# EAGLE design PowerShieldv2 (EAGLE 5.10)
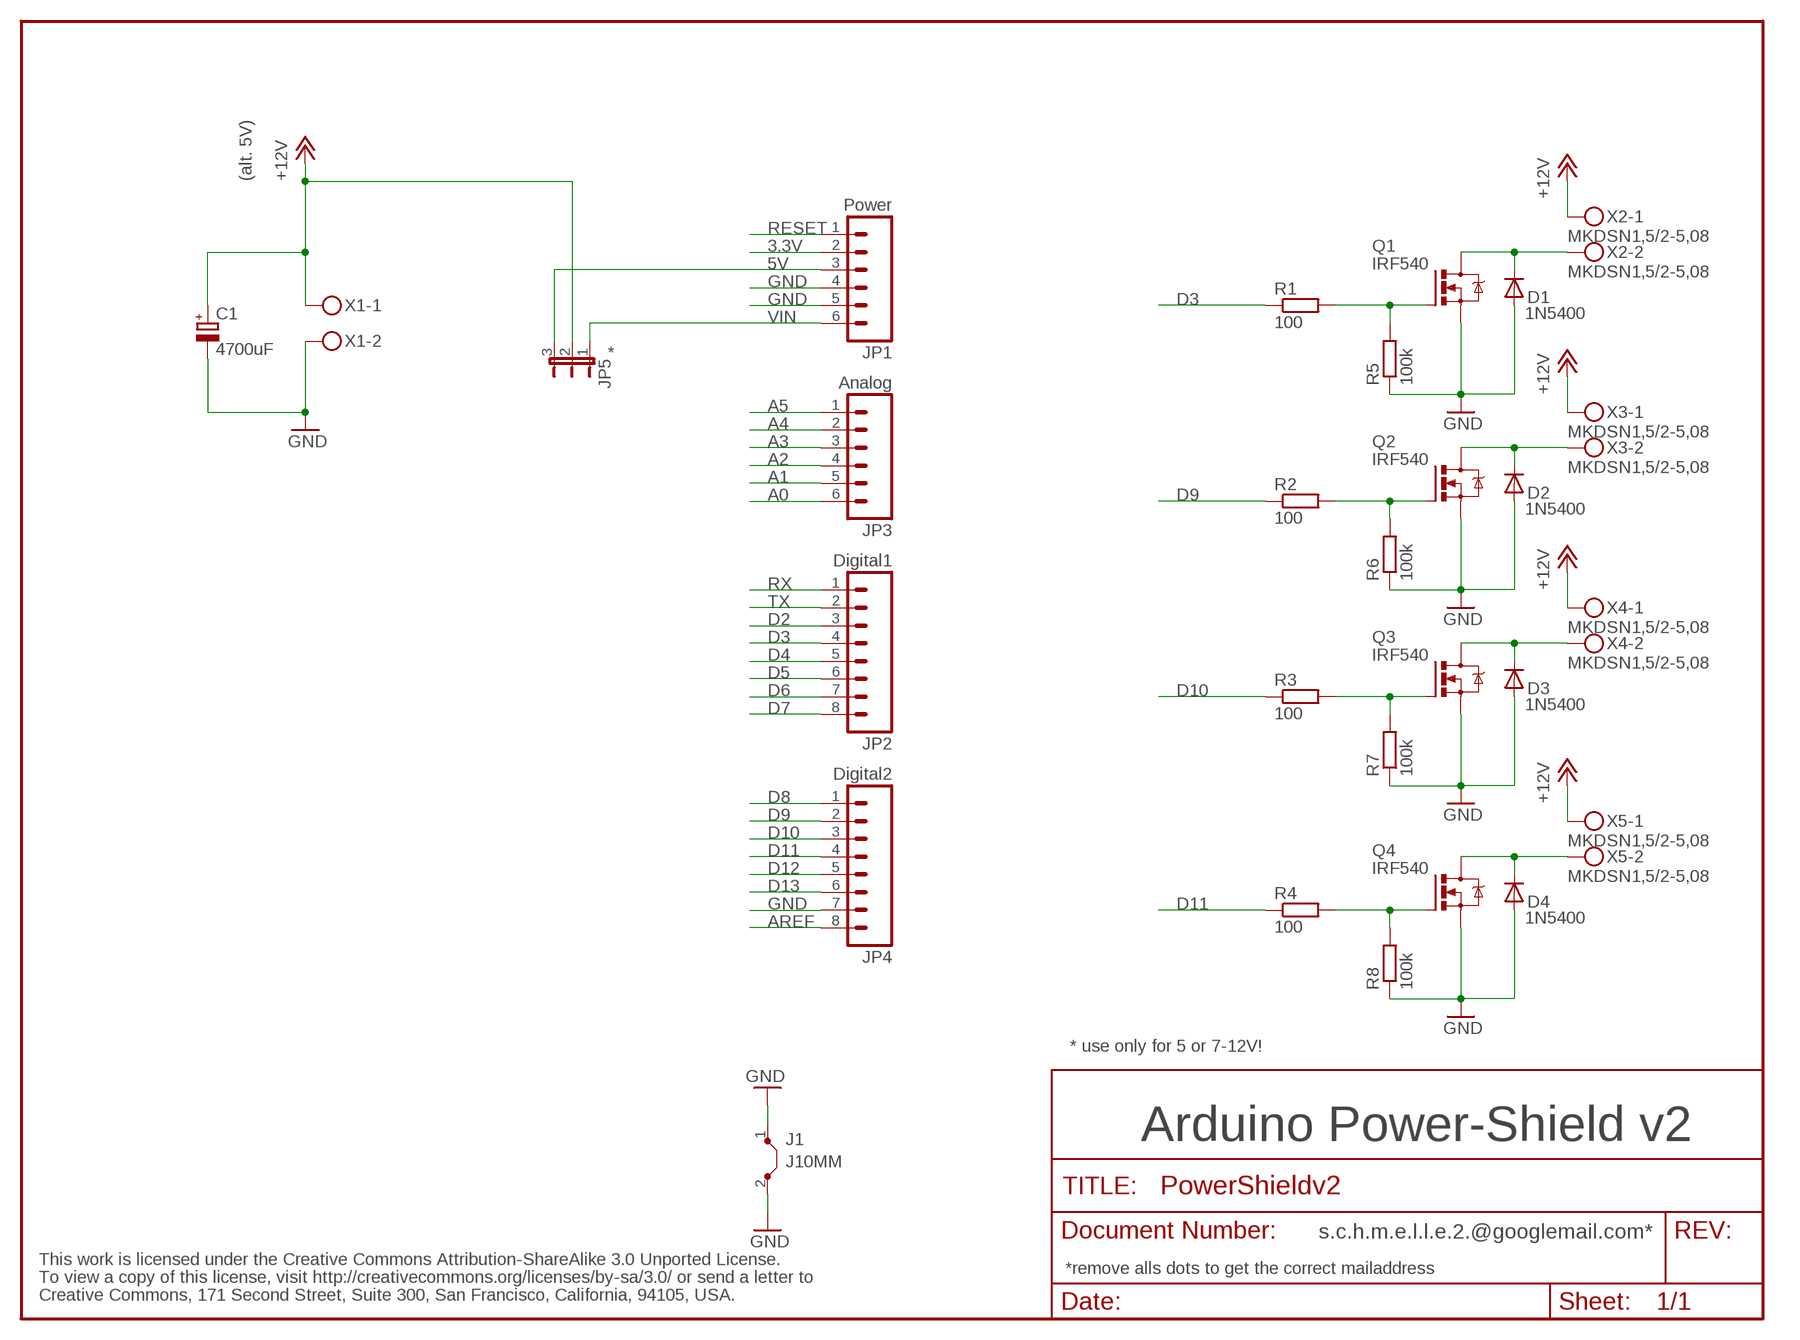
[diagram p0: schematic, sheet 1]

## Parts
C1  4700uF  CPOL-EUE35-16AXIAL  [E35-16]
D1  1N5400  [DO201-15]
D2  1N5400  [DO201-15]
D3  1N5400  [DO201-15]
D4  1N5400  [DO201-15]
J1  J10MM  [10]
JP1  Power  M06SIP  [1X06]
JP2  Digital1  M08  [1X08]
JP3  Analog  M06SIP  [1X06]
JP4  Digital2  M08  [1X08]
JP5  JP2E  [JP2]
Q1  IRF540  [TO220BV]
Q2  IRF540  [TO220BV]
Q3  IRF540  [TO220BV]
Q4  IRF540  [TO220BV]
R1  100  R-EU_0411/12  [0411/12]
R2  100  R-EU_0411/12  [0411/12]
R3  100  R-EU_0411/12  [0411/12]
R4  100  R-EU_0411/12  [0411/12]
R5  100k  R-EU_0411/12  [0411/12]
R6  100k  R-EU_0411/12  [0411/12]
R7  100k  R-EU_0411/12  [0411/12]
R8  100k  R-EU_0411/12  [0411/12]
X1  MKDSN1,5/2-5,08  [MKDSN1,5/2-5,08]
X2  MKDSN1,5/2-5,08  [MKDSN1,5/2-5,08]
X3  MKDSN1,5/2-5,08  [MKDSN1,5/2-5,08]
X4  MKDSN1,5/2-5,08  [MKDSN1,5/2-5,08]
X5  MKDSN1,5/2-5,08  [MKDSN1,5/2-5,08]

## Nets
3.3V: JP1.2
5V [power]: JP1.3 JP5.3
+12V: C1.+ JP5.2 X1.1 X2.1 X3.1 X4.1 X5.1
A0: JP3.6
A1: JP3.5
A2: JP3.4
A3: JP3.3
A4: JP3.2
A5: JP3.1
AREF: JP4.8
D2: JP2.3
D3: JP2.4 R1.1
D4: JP2.5
D5: JP2.6
D6: JP2.7
D7: JP2.8
D8: JP4.1
D9: JP4.2 R2.1
D10: JP4.3 R3.1
D11: JP4.4 R4.1
D12: JP4.5
D13: JP4.6
GND [power]: C1.- D1.A D2.A D3.A D4.A J1.1 J1.2 JP1.4 JP1.5 JP4.7 Q1.S Q2.S Q3.S Q4.S R5.1 R6.1 R7.1 R8.1 X1.2
N$1: D1.C Q1.D X2.2
N$2: Q1.G R1.2 R5.2
N$3: D2.C Q2.D X3.2
N$4: Q2.G R2.2 R6.2
N$5: D3.C Q3.D X4.2
N$6: Q3.G R3.2 R7.2
N$7: D4.C Q4.D X5.2
N$8: Q4.G R4.2 R8.2
RESET: JP1.1
RX: JP2.1
TX: JP2.2
VIN [power]: JP1.6 JP5.1

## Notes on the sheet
- (alt. 5V)
- *
- * use only for 5 or 7-12V!
- Arduino Power-Shield v2
- s.c.h.m.e.l.l.e.2.@googlemail.com*
- This work is licensed under the Creative Commons Attribution-ShareAlike 3.0 Unported License.
- *remove alls dots to get the correct mailaddress
- To view a copy of this license, visit http://creativecommons.org/licenses/by-sa/3.0/ or send a letter to
- Creative Commons, 171 Second Street, Suite 300, San Francisco, California, 94105, USA.

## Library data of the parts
C1 = resistor:CPOL-EU: POLARIZED CAPACITOR, European symbol
D1-D4 = diode:1N5400: DIODE
J1 = jumper:J: Bridge
JP1 JP3 = SparkFun:M06: Header 6 Standard 6-pin 0.1" header. Use with straight break away headers (SKU : PRT-00116), right angle break away headers (PRT-00553), swiss pins (PRT-00743), machine pins (PRT-00117), and female headers (PRT-00115). Molex polarized connector foot print use with SKU : PRT-08094 with associated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
JP2 JP4 = SparkFun:M08: Header 8 Standard 8-pin 0.1" header. Use with straight break away headers (SKU : PRT-00116), right angle break away headers (PRT-00553), swiss pins (PRT-00743), machine pins (PRT-00117), and female headers (PRT-00115).
JP5 = jumper:JP2E: JUMPER
Q1-Q4 = transistor-power:IRF540: HEXFET Power MOSFET
R1-R8 = resistor:R-EU_: RESISTOR, European symbol
X1-X5 = con-phoenix-508:MKDSN1,5/2-5,08: MKDSN 1,5/ 2-5,08 Printklemme

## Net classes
1 power: width 0.254 mm

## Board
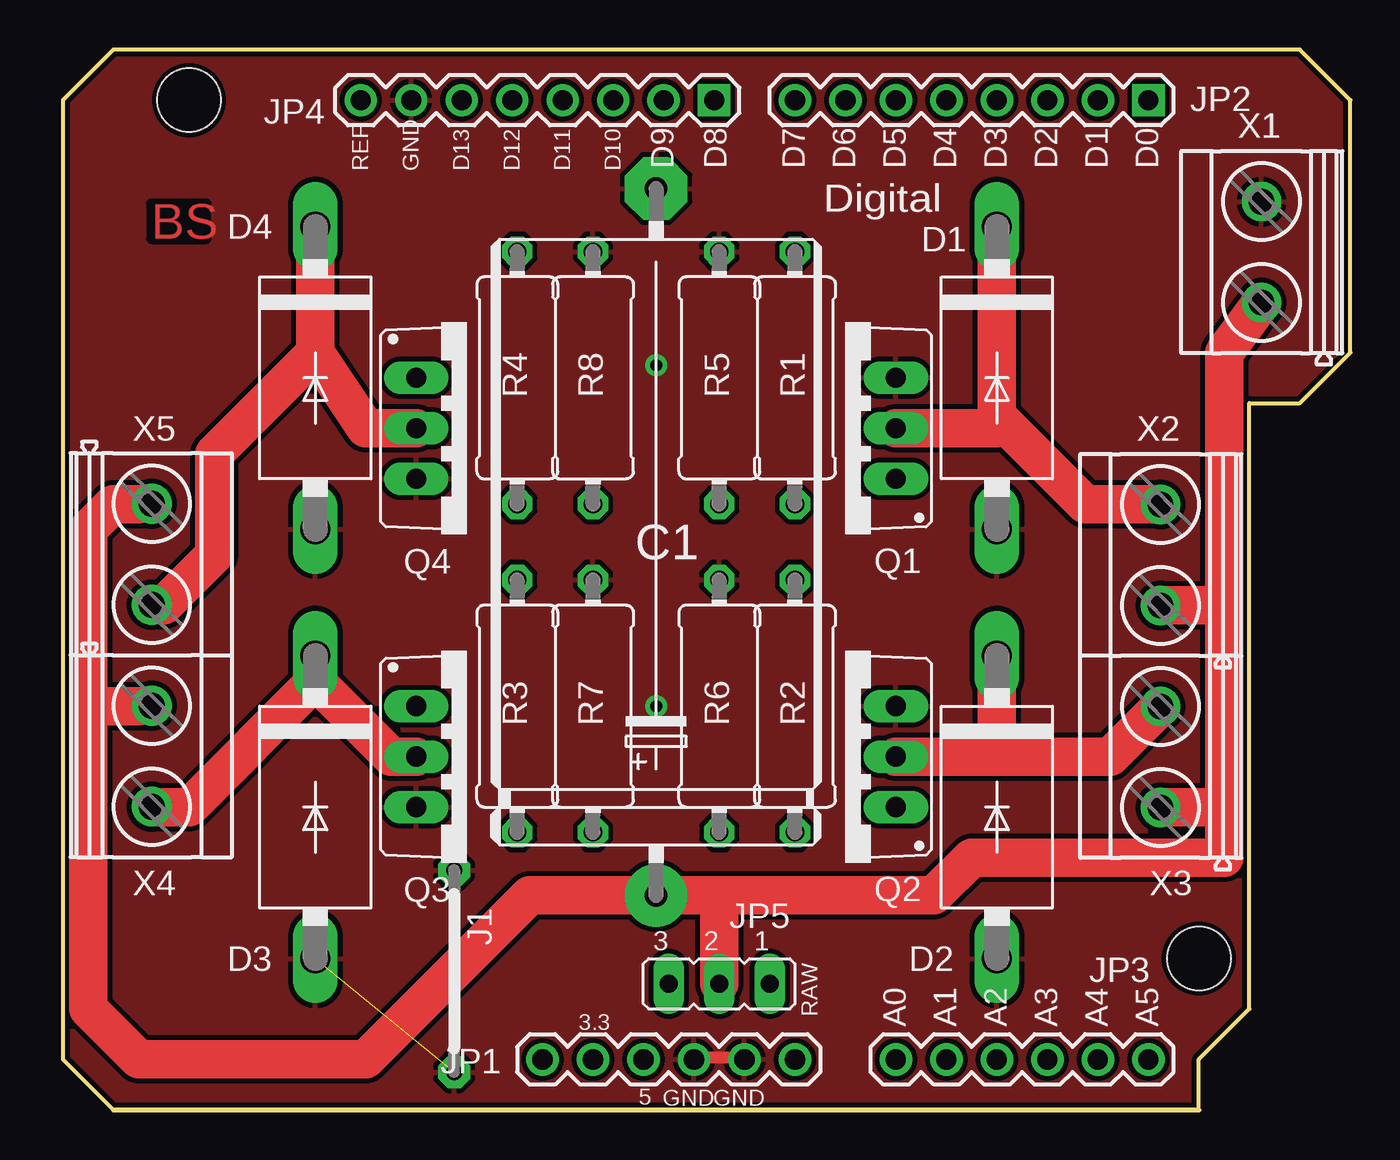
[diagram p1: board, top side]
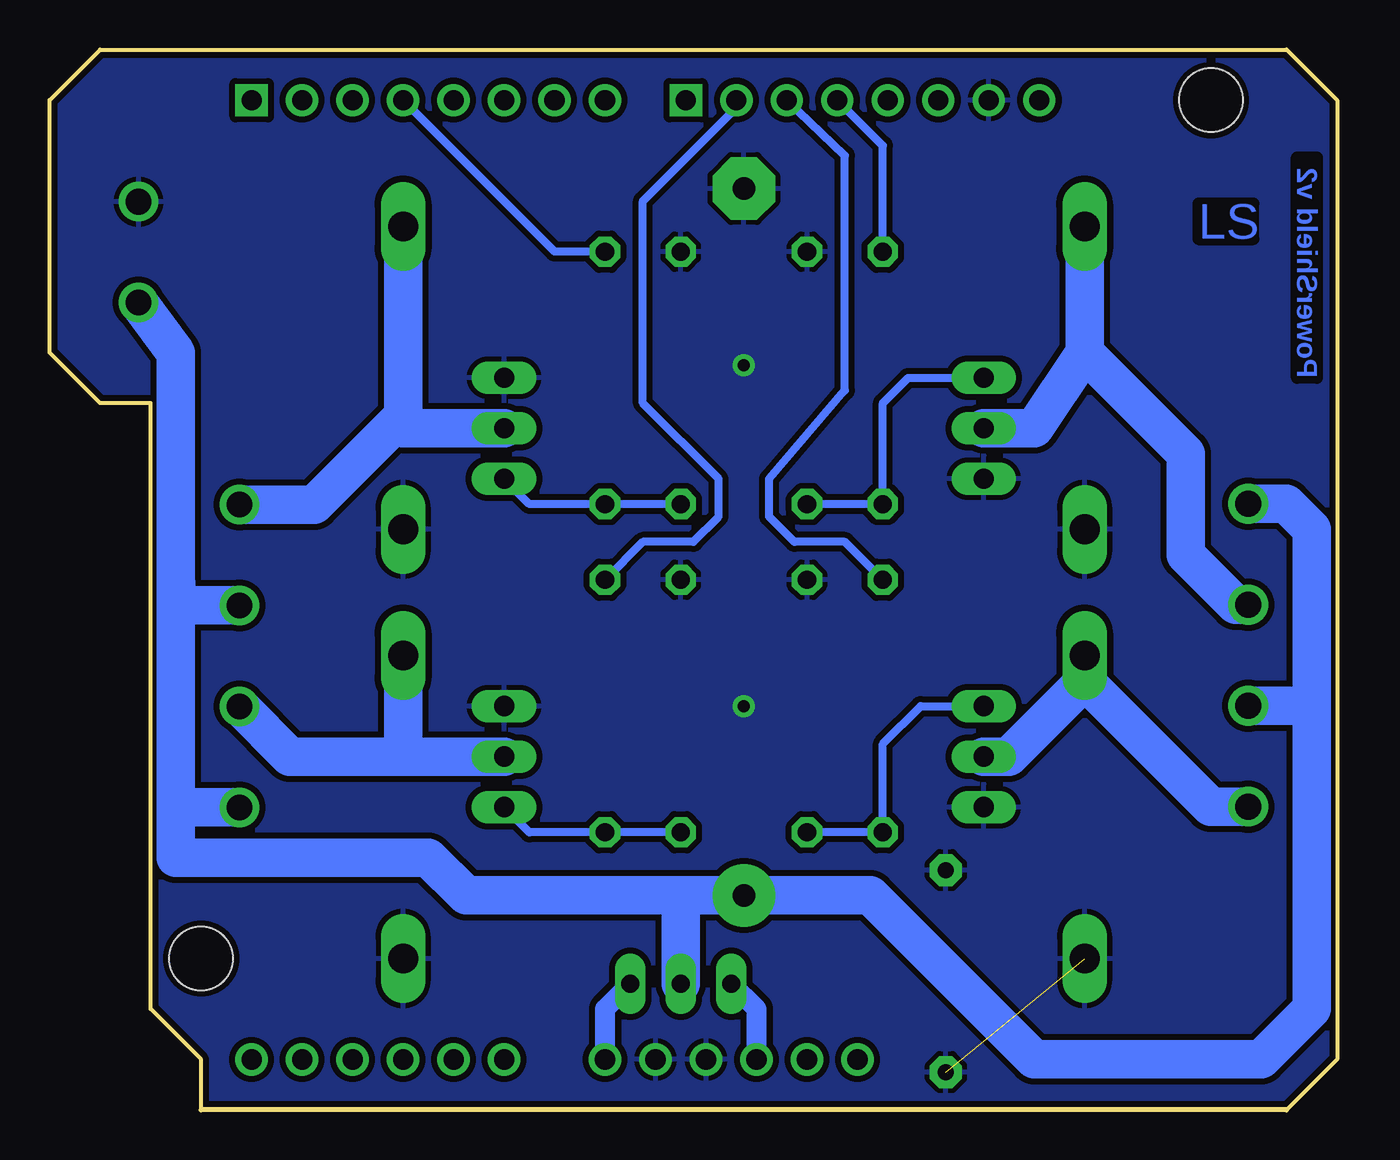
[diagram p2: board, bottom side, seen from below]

Size 64.77 x 53.34 mm. Coordinates in mm from the lower left corner, seen from the top.
Outline: 0,50.8 0,2.54 2.54,0 57.15,0 57.15,2.54 59.69,5.08 59.69,35.56 62.23,35.56 64.77,38.1 64.77,50.8 62.23,53.34 2.54,53.34 0,50.8
Copper layers (1*16): Top 0.035mm / dielectric 1.5mm / Bottom 0.035mm
Design rules "SparkFun": minimum track width 8mil, minimum drill 20mil, track to track 8mil, track to pad 8mil, pad to pad 8mil, via to via 8mil, smd to smd 8mil, copper to edge 10mil, drill to drill 8mil, minimum pad ring 12mil, minimum via ring 10mil, stop-mask expansion 4mil, vias tented up to drill 20mil, thermal gap 10mil
Holes 3.2 mm at 57.15,7.62 6.35,50.8

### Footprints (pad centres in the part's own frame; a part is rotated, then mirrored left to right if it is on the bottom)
E35-16 = drill 1.118 pad 3.15 round: + -17.78,0 | drill 1.118 pad 3.15 octagon: - 17.78,0
DO201-15 = drill 1.499 long: A 7.62,0; C -7.62,0
10 = drill 0.813 pad 1.6 octagon: 1 -5.08,0; 2 5.08,0
1X06 = drill 1.016 round: 1 0,0; 2 2.54,0; 3 5.08,0; 4 7.62,0; 5 10.16,0; 6 12.7,0
1X08 = drill 1.016 square: 1 0,0 | drill 1.016 round: 2 2.54,0; 3 5.08,0; 4 7.62,0; 5 10.16,0; 6 12.7,0; 7 15.24,0; 8 17.78,0
JP2 = drill 0.914 long: 1 -2.54,0; 2 0,0; 3 2.54,0
TO220BV = drill 1.016 long: D 0,-2.54; G -2.54,-2.54; S 2.54,-2.54
0411/12 = drill 0.914 octagon: 1 -6.35,0; 2 6.35,0
MKDSN1,5/2-5,08 = drill 1.3 pad 2 round: 1 -2.561,0.025; 2 2.519,0.025

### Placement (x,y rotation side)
C1  29.84,28.57 90 top
D1  46.99,36.83 270 top
D2  46.99,15.24 270 top
D3  12.7,15.24 270 top
D4  12.7,36.83 270 top
J1  19.68,6.99 270 top
JP1  24.13,2.54 0 top
JP2  54.61,50.8 180 top
JP3  54.61,2.54 180 top
JP4  32.77,50.8 180 top
JP5  33.02,6.35 180 top
Q1  39.37,34.29 90 top
Q2  39.37,17.78 90 top
Q3  20.32,17.78 270 top
Q4  20.32,34.29 270 top
R1  36.83,36.83 270 top
R2  36.83,20.32 270 top
R3  22.86,20.32 270 top
R4  22.86,36.83 270 top
R5  33.02,36.83 270 top
R6  33.02,20.32 270 top
R7  26.67,20.32 270 top
R8  26.67,36.83 270 top
X1  60.33,43.18 90 top
X2  55.24,27.94 90 top
X3  55.24,17.78 90 top
X4  4.45,17.78 270 top
X5  4.45,27.94 270 top

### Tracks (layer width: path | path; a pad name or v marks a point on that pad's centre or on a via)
5V
  Bottom 1.016: JP1.3 29.21,5.08 JP5.3
+12V
  Top 1.93: 58.42,15.24 58.42,12.7 45.72,12.7 43.81,10.79 33.02,10.79 | 58.42,15.24 58.42,27.3 | 33.02,10.79 JP5.2 | 33.02,10.79 C1.+ 23.5,10.79 15.24,2.54 3.81,2.54 1.27,5.08 1.27,20.32 | 1.27,20.32 3.81,20.32 | 1.27,20.32 1.27,29.21 2.54,30.48 3.81,30.48 | 58.42,15.24 55.24,15.24
  Bottom 1.93: X1.1 58.42,38.1 58.42,27.94 | 58.42,27.94 58.4,25.38 X2.1 | 58.42,27.94 58.42,15.24 X3.1 58.42,15.24 58.42,12.7 45.72,12.7 43.81,10.79 33.02,10.79 | 33.02,10.79 C1.+ 23.5,10.79 15.24,2.54 3.81,2.54 1.27,5.08 1.27,20.34 | 33.02,10.79 JP5.2 | X5.1 2.56,30.5 1.27,29.21 1.27,20.34 | 1.27,20.34 X4.1
D3
  Bottom 0.406: JP2.4 39.37,43.18 R1.1
D9
  Bottom 0.406: JP4.2 30.48,50.8 30.48,50.16 34.92,45.72 34.92,35.56 31.11,31.75 31.11,29.84 32.38,28.57 34.92,28.57 R2.1
D10
  Bottom 0.406: JP4.3 24.77,48.01 24.77,36.2 28.57,31.75 28.57,29.84 27.3,28.57 24.77,28.57 R3.1
D11
  Bottom 0.406: JP4.4 22.86,48.51 R4.1
GND  (via drill 0.6)  (1 unrouted)
  Top 0.61: JP1.4 32.36,2.64 33.58,2.64 JP1.5
  other vias: 29.84,37.47 29.84,20.32
  pour Bottom (isolate 0.305): 64.77,53.34 64.77,0 0,0 0,53.34
  pour Top (isolate 0.254): 2.54,53.34 0,50.8 0,2.54 2.54,0 57.15,0 57.15,2.54 59.69,5.08 59.69,35.56 62.23,35.56 64.77,38.1 64.77,50.8 62.23,53.34
N$1
  Top 1.93: 46.99,34.92 D1.C | 46.99,34.92 46.99,34.29 Q1.D | 55.24,30.48 51.44,30.48 46.99,34.92
  Bottom 1.93: 46.99,34.92 D1.C | 46.99,34.92 46.99,34.29 Q1.D | X2.2 51.46,30.46 46.99,34.92
N$2
  Bottom 0.406: Q1.G 40.64,30.48 R1.2 R5.2
N$3
  Top 1.93: 55.24,20.32 52.7,17.78 46.99,17.78 | Q2.D 46.99,17.78 | 46.99,17.78 D2.C
  Bottom 1.93: 46.99,17.78 D2.C | Q2.D 46.99,17.78 | X3.2 52.7,17.78 46.99,17.78
N$4
  Bottom 0.406: R6.2 R2.2 40.64,13.97 Q2.G
N$5
  Top 1.93: Q3.D 16.51,17.78 12.7,21.59 | D3.C 12.7,21.59 | 4.45,15.24 6.35,15.24 12.7,21.59
  Bottom 1.93: Q3.D 16.51,17.78 12.7,21.59 | 12.7,21.59 D3.C | X4.2 6.37,15.26 12.7,21.59
N$6
  Bottom 0.406: R7.2 R3.2 22.86,18.41 20.95,20.32 Q3.G
N$7
  Top 1.93: D4.C 12.7,38.1 | 12.7,38.1 15.24,34.29 Q4.D | 12.7,38.1 7.62,33.02 7.62,27.94 5.08,25.4 4.45,25.4
  Bottom 1.93: Q4.D 15.24,34.29 12.7,38.1 | 12.7,38.1 D4.C | X5.2 5.1,25.42 7.62,27.94 7.62,33.02 12.7,38.1
N$8
  Bottom 0.406: R8.2 R4.2 22.86,35.56 21.59,36.83 Q4.G
N$9
  Top 1.93: 60.33,40.64 58.42,38.1 58.42,25.4 55.24,25.4
VIN
  Bottom 1.016: JP1.6 36.83,5.08 JP5.1

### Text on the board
Top: BS
Bottom: LS | PowerShield v2
tPlace: REF | GND | D13 | D12 | D11 | D10 | D9 | D8 | D7 | D6 | D5 | D4 | D3 | D2 | D1 | D0 | 3.3 | RAW | A0 | A1 | A2 | A3 | A4 | A5 | GND | GND | 5
tNames: Digital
